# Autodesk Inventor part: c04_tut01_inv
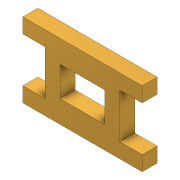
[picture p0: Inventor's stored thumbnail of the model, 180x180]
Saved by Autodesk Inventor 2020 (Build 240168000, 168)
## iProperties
Created: 2019-02
Part Number: c04_tut01_inv
Material: Brass, Soft Yellow
Document SubType Name: Modeling
Designer: LENOVO-CADCIM
Density: 8.47 g/cm^3
Appearance: Brass - Satin
Author: LENOVO-CADCIM
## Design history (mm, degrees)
sketch "Sketch1"
  geometry: L1 (0, 0)-(80, 0); L2 (80, 0)-(80, 10); L3 (80, 10)-(65, 10); L4 (65, 10)-(65, 40); L5 (65, 40)-(80, 40); L6 (80, 40)-(80, 50); L7 (80, 50)-(0, 50); L8 (0, 50)-(0, 40); L9 (0, 40)-(15, 40); L10 (15, 40)-(15, 10); L11 (15, 10)-(0, 10); L12 (0, 10)-(0, 0); L13 (25, 15)-(55, 15); L14 (55, 15)-(55, 35); L15 (55, 35)-(25, 35); L16 (25, 35)-(25, 15); 1 further point
  constraints: 32 end point, 6 perpendicular, 6 point on line, 2 horizontal, 2 parallel, 1 coincident, 1 collinear
  dimensions: "d0" = 80 distance of L1.start L1.end; "d1" = 10 distance of L1.end L2.end; "d2" = 15 distance of L2.end L3.end; "d3" = 30 distance of L3.end L4.end; "d4" = 15 distance of L4.end L5.end; "d5" = 10 distance of L5.end L6.end; "d6" = 80 distance of L6.end L7.end; "d7" = 10 distance of L7.end L8.end (derived); "d8" = 15 distance of L8.end L9.end; "d9" = 30 distance of L9.end L10.end (derived); "d10" = 15 distance of L10.end L11.end; "d11" = 30 distance of L15.end L14.end; "d12" = 20 distance of L14.end L13.end; "d14" = 15 distance between parallel lines of L13 L1; "d15" = 10 distance between parallel lines of L14 L4
extrude "Extrusion1" new body sketch "Sketch1" distance "d16" = 10; taper "d17" = 0 deg
body "Solid1"
